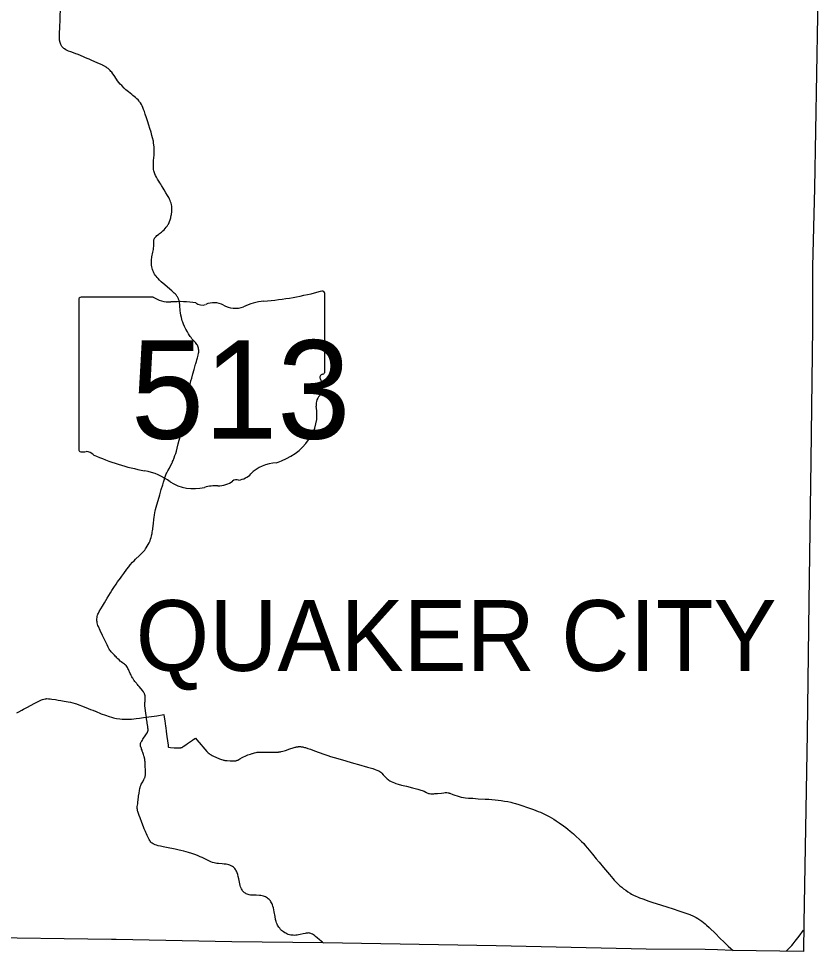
# Model space of a CAD drawing. Extents: x 1761803 to 2441803, y 509895 to 949895.
# Drawn here: x 2301181 to 2323804, y 808156 to 834521 of the extents above; entities that cross this region are included whole.
import ezdxf

# ---------------------------------------------------------------- set-up
doc = ezdxf.new("R2010")
doc.units = 0
for name, color, linetype in [('GM_X_County', 7, 'Continuous'), ('GM_X_County_Road', 7, 'Continuous'), ('GM_X_Minor_Lake', 7, 'Continuous'), ('GM_X_Township_Road', 7, 'Continuous')]:
    doc.layers.add(name, color=color, linetype=linetype)

msp = doc.modelspace()

# ---------------------------------------------------------------- linework, layer by layer
at = {"layer": 'GM_X_County'}
msp.add_lwpolyline([(2323804, 836223), (2323694, 829731), (2323638, 827518), (2323640, 825800), (2323587, 822019), (2323538, 818035), (2323488, 814313), (2323389, 808951), (2323379, 808156), (2321372, 808183), (2320947, 808195), (2320606, 808207), (2318933, 808214), (2314690, 808308), (2309795, 808393), (2307209, 808423), (2303944, 808491), (2303812, 808492), (2299788, 808546)], dxfattribs=at)
at = {"layer": 'GM_X_Minor_Lake'}
for points in [[(2303174, 833376), (2303124, 833396), (2303058, 833425), (2302914, 833485), (2302838, 833514), (2302795, 833530), (2302732, 833552), (2302657, 833579), (2302590, 833605), (2302538, 833630), (2302515, 833642), (2302480, 833665), (2302458, 833682), (2302438, 833700), (2302421, 833718), (2302415, 833726), (2302406, 833738), (2302388, 833768), (2302379, 833786), (2302374, 833795), (2302366, 833816), (2302364, 833819), (2302356, 833843), (2302353, 833853), (2302349, 833870), (2302347, 833883), (2302345, 833892), (2302342, 833908), (2302340, 833935), (2302338, 833982), (2302340, 834041), (2302342, 834110), (2302348, 834272), (2302352, 834497), (2302361, 834861)], [(2303890, 816530), (2303826, 816598), (2303799, 816627), (2303780, 816650), (2303763, 816674), (2303745, 816702), (2303716, 816754), (2303683, 816818), (2303635, 816915), (2303554, 817087), (2303488, 817230), (2303440, 817335), (2303425, 817371), (2303413, 817406), (2303405, 817438), (2303399, 817467), (2303396, 817497), (2303396, 817500), (2303395, 817527), (2303396, 817560), (2303399, 817593), (2303401, 817603), (2303405, 817626), (2303414, 817658), (2303426, 817689), (2303439, 817719), (2303462, 817763), (2303505, 817840), (2303549, 817913), (2303609, 818011), (2303687, 818141), (2303733, 818216), (2303779, 818292), (2303819, 818359), (2303852, 818412), (2303873, 818445), (2303936, 818538), (2303981, 818602), (2304060, 818707), (2304097, 818757), (2304155, 818837), (2304243, 818955), (2304297, 819026), (2304341, 819079), (2304405, 819153), (2304446, 819196), (2304490, 819241), (2304597, 819342), (2304647, 819389), (2304684, 819427), (2304719, 819466), (2304748, 819501), (2304771, 819532), (2304792, 819562), (2304819, 819606), (2304848, 819657), (2304872, 819704), (2304899, 819763), (2304916, 819806), (2304932, 819852), (2304943, 819896), (2304952, 819937), (2304957, 819966), (2304963, 820005), (2304969, 820047), (2304974, 820086), (2304979, 820122), (2304984, 820164), (2304989, 820210), (2304992, 820236), (2304998, 820291), (2305002, 820324), (2305007, 820366), (2305017, 820428), (2305025, 820486), (2305036, 820561), (2305043, 820599), (2305054, 820647), (2305072, 820714), (2305118, 820868), (2305158, 820996), (2305176, 821059), (2305217, 821211), (2305256, 821344), (2305278, 821419), (2305304, 821507), (2305319, 821554), (2305336, 821600), (2305358, 821651), (2305373, 821683), (2305400, 821736), (2305446, 821819), (2305491, 821899), (2305523, 821963), (2305532, 821985), (2305538, 821999), (2305550, 822033), (2305579, 822103), (2305604, 822171), (2305624, 822233), (2305644, 822299), (2305666, 822384), (2305696, 822505), (2305723, 822603), (2305739, 822660), (2305752, 822711), (2305826, 822973), (2305841, 823026), (2305850, 823063), (2305865, 823127), (2305877, 823175), (2305916, 823318), (2305952, 823457), (2305967, 823521), (2305981, 823595), (2305992, 823666), (2306000, 823734), (2306006, 823806), (2306016, 823950), (2306025, 824084), (2306033, 824153), (2306038, 824192), (2306046, 824234), (2306056, 824279), (2306077, 824359), (2306112, 824485), (2306144, 824599), (2306166, 824677), (2306187, 824750), (2306194, 824772), (2306209, 824826), (2306222, 824873), (2306242, 824935), (2306260, 825005), (2306272, 825062), (2306277, 825098), (2306278, 825123), (2306277, 825136), (2306276, 825149), (2306273, 825181), (2306267, 825210), (2306259, 825238), (2306249, 825265), (2306237, 825288), (2306222, 825313), (2306204, 825340), (2306181, 825367), (2306149, 825404), (2306084, 825474), (2306059, 825504), (2306036, 825533), (2306012, 825568), (2305984, 825612), (2305954, 825664), (2305915, 825740), (2305877, 825820), (2305847, 825885), (2305826, 825937), (2305811, 825981), (2305799, 826022), (2305787, 826073), (2305774, 826140), (2305763, 826208), (2305755, 826260), (2305752, 826279), (2305749, 826315), (2305745, 826355), (2305738, 826443), (2305731, 826488), (2305722, 826539), (2305718, 826556), (2305713, 826574), (2305708, 826588), (2305702, 826604), (2305695, 826622), (2305688, 826637), (2305678, 826654), (2305670, 826668), (2305661, 826681), (2305649, 826696), (2305637, 826711), (2305610, 826739), (2305581, 826766), (2305513, 826826), (2305393, 826928), (2305319, 826993), (2305214, 827086), (2305164, 827133), (2305125, 827173), (2305096, 827205), (2305069, 827238), (2305046, 827270), (2305025, 827303), (2305009, 827332), (2304994, 827362), (2304978, 827402), (2304969, 827430), (2304959, 827468), (2304949, 827510), (2304942, 827549), (2304938, 827585), (2304937, 827613), (2304936, 827637), (2304938, 827683), (2304941, 827723), (2304945, 827759), (2304951, 827788), (2304962, 827836), (2304971, 827871), (2304982, 827922), (2304995, 827996), (2305001, 828041), (2305004, 828076), (2305004, 828115), (2305004, 828133), (2305003, 828151), (2305002, 828194), (2305003, 828226), (2305006, 828249), (2305007, 828260), (2305010, 828271), (2305014, 828284), (2305014, 828286), (2305024, 828307), (2305029, 828317), (2305038, 828329), (2305052, 828346), (2305068, 828362), (2305095, 828387), (2305139, 828422), (2305167, 828444), (2305218, 828486), (2305259, 828522), (2305295, 828556), (2305328, 828592), (2305356, 828624), (2305379, 828655), (2305404, 828693), (2305417, 828716), (2305437, 828757), (2305451, 828790), (2305469, 828839), (2305478, 828867), (2305484, 828891), (2305489, 828914), (2305499, 828959), (2305503, 828983), (2305507, 829007), (2305512, 829049), (2305514, 829071), (2305516, 829092), (2305517, 829114), (2305516, 829140), (2305515, 829176), (2305511, 829215), (2305502, 829266), (2305494, 829301), (2305481, 829341), (2305466, 829381), (2305447, 829422), (2305427, 829463), (2305391, 829526), (2305349, 829596), (2305299, 829681), (2305272, 829725), (2305226, 829801), (2305200, 829842), (2305176, 829880), (2305144, 829931), (2305128, 829958), (2305112, 829983), (2305077, 830043), (2305051, 830092), (2305034, 830131), (2305023, 830159), (2305014, 830188), (2305006, 830223), (2304999, 830259), (2304996, 830305), (2304995, 830345), (2304995, 830391), (2304996, 830433), (2304999, 830476), (2305001, 830519), (2305004, 830574), (2305012, 830675), (2305013, 830711), (2305014, 830757), (2305015, 830806), (2305014, 830848), (2305012, 830900), (2305008, 830949), (2305001, 831007), (2304992, 831057), (2304970, 831151), (2304953, 831221), (2304927, 831312), (2304895, 831416), (2304865, 831506), (2304823, 831637), (2304797, 831715), (2304762, 831822), (2304738, 831893), (2304714, 831957), (2304695, 832007), (2304675, 832054), (2304654, 832095), (2304629, 832137), (2304604, 832172), (2304588, 832193), (2304559, 832225), (2304525, 832256), (2304483, 832294), (2304413, 832349), (2304380, 832376), (2304291, 832448), (2304218, 832509), (2304193, 832530), (2304165, 832557), (2304096, 832627), (2304058, 832668), (2304020, 832713), (2303982, 832762), (2303947, 832812), (2303883, 832910), (2303849, 832962), (2303817, 833005), (2303794, 833032), (2303768, 833060), (2303742, 833086), (2303712, 833111), (2303679, 833135), (2303673, 833139), (2303642, 833159), (2303633, 833165), (2303595, 833186), (2303551, 833208), (2303540, 833214), (2303465, 833248), (2303338, 833305), (2303233, 833351), (2303176, 833375), (2303174, 833376)], [(2304753, 815194), (2304756, 815217), (2304758, 815233), (2304759, 815247), (2304760, 815261), (2304762, 815279), (2304762, 815292), (2304763, 815310), (2304763, 815319), (2304763, 815331), (2304762, 815344), (2304762, 815352), (2304761, 815360), (2304761, 815365), (2304760, 815370), (2304759, 815374), (2304758, 815379), (2304757, 815387), (2304756, 815391), (2304755, 815396), (2304753, 815403), (2304753, 815407), (2304751, 815411), (2304750, 815415), (2304749, 815418), (2304748, 815422), (2304746, 815426), (2304738, 815444), (2304734, 815452), (2304725, 815469), (2304712, 815490), (2304682, 815530), (2304644, 815578), (2304591, 815641), (2304565, 815671), (2304542, 815698), (2304524, 815721), (2304511, 815736), (2304497, 815753), (2304487, 815765), (2304471, 815784), (2304451, 815810), (2304444, 815819), (2304428, 815843), (2304408, 815876), (2304400, 815891), (2304384, 815920), (2304369, 815952), (2304356, 815979), (2304339, 816013), (2304320, 816055), (2304310, 816079), (2304292, 816121), (2304274, 816156), (2304258, 816184), (2304239, 816211), (2304221, 816233), (2304203, 816251), (2304194, 816260), (2304180, 816272), (2304152, 816293), (2304120, 816315), (2304085, 816340), (2304057, 816362), (2304022, 816393), (2303989, 816425), (2303961, 816453), (2303936, 816479), (2303914, 816503), (2303890, 816530)], [(2301134, 814903), (2301185, 814931), (2301270, 814974), (2301323, 815001), (2301435, 815062), (2301622, 815158), (2301715, 815207), (2301793, 815247), (2301826, 815263), (2301856, 815274), (2301890, 815285), (2301928, 815294), (2301957, 815298), (2301979, 815299), (2302025, 815298), (2302074, 815293), (2302116, 815288), (2302221, 815271), (2302301, 815257), (2302372, 815245)], [(2302372, 815245), (2302379, 815244), (2302466, 815230), (2302586, 815209), (2302644, 815198), (2302714, 815181), (2302777, 815163), (2302817, 815151), (2302885, 815126), (2302986, 815087), (2303144, 815024), (2303214, 814997), (2303281, 814970), (2303343, 814944), (2303351, 814941)], [(2303351, 814941), (2303518, 814874), (2303638, 814830), (2303738, 814796), (2303807, 814774), (2303864, 814759), (2303906, 814750), (2303954, 814741), (2304042, 814729), (2304114, 814721), (2304177, 814718), (2304243, 814716), (2304266, 814717)], [(2304752, 815088), (2304752, 815091), (2304751, 815100), (2304750, 815112), (2304750, 815124), (2304749, 815135), (2304749, 815146), (2304750, 815156), (2304750, 815162), (2304750, 815168), (2304751, 815179), (2304753, 815194)], [(2304832, 814512), (2304825, 814559), (2304819, 814611), (2304815, 814633), (2304801, 814731), (2304795, 814778), (2304787, 814828), (2304780, 814880), (2304758, 815039), (2304752, 815088)], [(2304266, 814717), (2304308, 814717), (2304377, 814721), (2304440, 814727), (2304508, 814736), (2304605, 814750), (2304771, 814774), (2304795, 814778)], [(2304795, 814778), (2304865, 814785), (2305011, 814807), (2305092, 814818), (2305292, 814853)], [(2305292, 814853), (2305302, 814774), (2305308, 814733), (2305318, 814662), (2305326, 814604), (2305339, 814510)], [(2304684, 814132), (2304699, 814155), (2304717, 814182), (2304736, 814209), (2304746, 814224), (2304760, 814246), (2304778, 814274), (2304795, 814302), (2304822, 814346), (2304829, 814358), (2304834, 814369), (2304837, 814378), (2304840, 814386), (2304842, 814398), (2304843, 814406), (2304843, 814414), (2304843, 814418), (2304843, 814427), (2304842, 814440), (2304839, 814463), (2304836, 814485), (2304832, 814512)], [(2305339, 814510), (2305342, 814489), (2305342, 814487), (2305357, 814373), (2305376, 814230), (2305407, 813989), (2305408, 813982), (2305409, 813976), (2305410, 813968), (2305410, 813967)], [(2306112, 814134), (2306140, 814152), (2306184, 814179), (2306219, 814138), (2306341, 813997), (2306393, 813938), (2306453, 813869), (2306504, 813810), (2306542, 813771), (2306569, 813747), (2306594, 813728), (2306624, 813709), (2306658, 813690), (2306696, 813672), (2306759, 813645), (2306868, 813600), (2306919, 813579), (2306956, 813567), (2306973, 813563), (2306993, 813558), (2307012, 813555), (2307032, 813552), (2307056, 813550), (2307080, 813549), (2307165, 813546), (2307247, 813544), (2307289, 813544), (2307305, 813544), (2307312, 813544)], [(2304726, 813012), (2304742, 813047), (2304748, 813062), (2304752, 813075), (2304756, 813088), (2304760, 813102), (2304764, 813119), (2304767, 813137), (2304768, 813154), (2304769, 813169), (2304770, 813188), (2304770, 813205), (2304768, 813286), (2304764, 813378), (2304762, 813469), (2304759, 813512), (2304755, 813544), (2304751, 813572), (2304748, 813589), (2304743, 813618), (2304740, 813636), (2304737, 813646), (2304735, 813655), (2304734, 813661), (2304732, 813666), (2304727, 813680), (2304714, 813717), (2304693, 813779), (2304680, 813819), (2304672, 813844), (2304661, 813875), (2304654, 813896), (2304649, 813909), (2304633, 813956), (2304631, 813964), (2304629, 813972), (2304627, 813981), (2304626, 813991), (2304625, 813998), (2304625, 814005), (2304625, 814012), (2304625, 814019), (2304627, 814026), (2304630, 814035), (2304632, 814043), (2304637, 814053), (2304642, 814064), (2304647, 814075), (2304654, 814087), (2304662, 814101), (2304681, 814129), (2304684, 814132)], [(2305410, 813967), (2305412, 813958), (2305413, 813952), (2305415, 813942), (2305418, 813931), (2305479, 813921), (2305581, 813913), (2305689, 813906), (2305719, 813905), (2305732, 813906), (2305747, 813908), (2305760, 813910), (2305772, 813912), (2305781, 813915), (2305788, 813917), (2305797, 813920), (2305805, 813923), (2305825, 813934), (2305838, 813943), (2305908, 813992), (2305956, 814027), (2306017, 814071), (2306096, 814124), (2306112, 814134)], [(2307312, 813544), (2307319, 813545), (2307330, 813546), (2307343, 813548), (2307354, 813552), (2307364, 813556), (2307373, 813560), (2307380, 813564), (2307434, 813596), (2307506, 813637), (2307541, 813655), (2307585, 813676), (2307625, 813692), (2307668, 813708), (2307737, 813730), (2307784, 813745), (2307799, 813750), (2307852, 813765), (2307900, 813778), (2307928, 813784), (2307955, 813787), (2307983, 813790), (2308014, 813791), (2308100, 813790), (2308212, 813787), (2308244, 813786), (2308303, 813785), (2308421, 813785), (2308486, 813787), (2308507, 813788), (2308528, 813790), (2308546, 813792), (2308570, 813796), (2308591, 813800), (2308611, 813804), (2308659, 813817), (2308731, 813838), (2308849, 813877), (2308949, 813909), (2309006, 813926), (2309026, 813931), (2309045, 813935), (2309059, 813938), (2309074, 813940), (2309085, 813942), (2309097, 813943), (2309112, 813944), (2309127, 813944), (2309139, 813944), (2309157, 813943), (2309173, 813941), (2309193, 813938), (2309217, 813933), (2309242, 813927), (2309266, 813922), (2309293, 813914), (2309362, 813894), (2309440, 813868), (2309505, 813844), (2309659, 813787), (2309680, 813779), (2309813, 813731), (2309930, 813690), (2310005, 813666), (2310106, 813637), (2310273, 813590), (2310440, 813541), (2310469, 813533), (2310658, 813479), (2310797, 813439), (2311048, 813365), (2311200, 813321), (2311269, 813299), (2311315, 813282), (2311346, 813269), (2311369, 813257), (2311395, 813242), (2311424, 813220), (2311454, 813193), (2311494, 813149), (2311538, 813100), (2311569, 813067), (2311603, 813036), (2311633, 813011), (2311651, 812998), (2311681, 812979), (2311721, 812957), (2311766, 812936), (2311811, 812918), (2311851, 812904), (2311917, 812884), (2312012, 812858), (2312155, 812823), (2312321, 812781), (2312473, 812741), (2312559, 812717), (2312596, 812706), (2312624, 812695), (2312651, 812682), (2312697, 812657), (2312719, 812645), (2312729, 812640), (2312753, 812629), (2312780, 812620), (2312808, 812614), (2312840, 812611), (2312882, 812610), (2312895, 812611), (2312931, 812613), (2312957, 812615), (2313029, 812621), (2313140, 812632), (2313211, 812641), (2313251, 812644), (2313277, 812645), (2313297, 812643), (2313331, 812638), (2313347, 812635), (2313362, 812631), (2313379, 812625), (2313468, 812593), (2313524, 812573), (2313586, 812551), (2313645, 812532), (2313703, 812518), (2313761, 812507), (2313826, 812498), (2313905, 812491), (2313997, 812484), (2314026, 812482), (2314177, 812472), (2314377, 812461), (2314478, 812454), (2314742, 812430), (2314833, 812419), (2314924, 812405), (2315021, 812388), (2315101, 812371), (2315158, 812357), (2315240, 812334), (2315334, 812306), (2315440, 812272), (2315546, 812235), (2315746, 812162), (2315878, 812112), (2315941, 812086), (2316016, 812053), (2316095, 812014), (2316192, 811965), (2316252, 811932), (2316319, 811891), (2316391, 811845), (2316470, 811792), (2316598, 811701), (2316662, 811655), (2316716, 811613), (2316787, 811554), (2316874, 811480), (2316954, 811407), (2317038, 811329), (2317108, 811260), (2317165, 811201), (2317209, 811152), (2317275, 811075), (2317416, 810907), (2317523, 810776)], [(2309807, 808391), (2309777, 808416), (2309751, 808435), (2309743, 808441), (2309690, 808485), (2309628, 808539), (2309581, 808580), (2309550, 808604), (2309521, 808624), (2309493, 808641), (2309467, 808654), (2309443, 808664), (2309419, 808670), (2309396, 808673), (2309377, 808675), (2309351, 808674), (2309319, 808670), (2309284, 808664), (2309227, 808650), (2309144, 808629), (2309099, 808619), (2309057, 808613), (2309020, 808609), (2308987, 808608), (2308948, 808609), (2308912, 808612), (2308879, 808617), (2308840, 808626), (2308806, 808637), (2308772, 808651), (2308739, 808666), (2308708, 808684), (2308674, 808706), (2308645, 808728), (2308620, 808749), (2308592, 808777), (2308566, 808807), (2308540, 808840), (2308521, 808868), (2308505, 808896), (2308490, 808926), (2308476, 808963), (2308464, 809001), (2308452, 809052), (2308434, 809139), (2308409, 809271), (2308387, 809383), (2308375, 809431), (2308363, 809468), (2308350, 809501), (2308336, 809531), (2308320, 809559), (2308306, 809580), (2308289, 809601), (2308267, 809624), (2308243, 809645), (2308217, 809664), (2308189, 809682), (2308161, 809697), (2308134, 809709), (2308104, 809720), (2308072, 809728), (2308037, 809733), (2307992, 809737), (2307903, 809740), (2307808, 809741), (2307775, 809743), (2307739, 809748), (2307706, 809754), (2307678, 809762), (2307650, 809772), (2307620, 809786), (2307597, 809799), (2307575, 809814), (2307554, 809831), (2307535, 809850), (2307518, 809871), (2307501, 809895), (2307486, 809921), (2307474, 809945), (2307460, 809979), (2307449, 810017), (2307438, 810062), (2307410, 810206), (2307394, 810273), (2307380, 810327), (2307367, 810371), (2307355, 810401), (2307342, 810427), (2307328, 810452), (2307313, 810474), (2307297, 810494), (2307276, 810514), (2307255, 810533), (2307228, 810552), (2307195, 810572), (2307173, 810584), (2307152, 810593), (2307125, 810601), (2307090, 810610), (2307049, 810617), (2306997, 810623), (2306942, 810627), (2306838, 810635), (2306789, 810641), (2306750, 810647), (2306708, 810657), (2306667, 810669), (2306621, 810687), (2306576, 810706), (2306508, 810739), (2306370, 810807), (2306317, 810832), (2306260, 810856), (2306193, 810882), (2306140, 810901), (2306078, 810921), (2305984, 810950), (2305858, 810985), (2305773, 811008), (2305719, 811021), (2305606, 811043), (2305364, 811088), (2305268, 811107), (2305191, 811125), (2305131, 811141), (2305080, 811157), (2305046, 811169), (2305003, 811186), (2304983, 811197), (2304957, 811213), (2304941, 811225), (2304922, 811243), (2304899, 811271), (2304890, 811285), (2304872, 811317), (2304851, 811357), (2304817, 811432), (2304797, 811474), (2304780, 811512), (2304767, 811541), (2304736, 811619), (2304714, 811673), (2304695, 811722), (2304683, 811753), (2304666, 811799), (2304616, 811927), (2304590, 811998), (2304571, 812054), (2304553, 812110), (2304548, 812129), (2304545, 812145), (2304542, 812159), (2304540, 812172), (2304539, 812186), (2304538, 812202), (2304538, 812212), (2304538, 812225), (2304539, 812236), (2304539, 812248), (2304549, 812326), (2304552, 812354), (2304555, 812378), (2304557, 812397), (2304560, 812420), (2304576, 812540), (2304590, 812629), (2304602, 812704), (2304611, 812755), (2304619, 812790), (2304623, 812806), (2304629, 812825), (2304635, 812841), (2304641, 812856), (2304652, 812880), (2304672, 812916), (2304691, 812949), (2304726, 813012)], [(2317523, 810776), (2317607, 810673), (2317726, 810529), (2317894, 810327), (2317987, 810217), (2318031, 810169), (2318047, 810151), (2318096, 810099), (2318143, 810053), (2318189, 810011), (2318240, 809968), (2318294, 809926), (2318356, 809882), (2318418, 809839), (2318477, 809803), (2318522, 809776), (2318578, 809747), (2318637, 809718), (2318691, 809694), (2318749, 809670), (2318835, 809638), (2319005, 809579), (2319089, 809551), (2319368, 809463), (2319521, 809414), (2319696, 809358), (2319855, 809305), (2320022, 809249), (2320115, 809216), (2320167, 809195), (2320191, 809186), (2320251, 809160), (2320305, 809135), (2320351, 809111), (2320396, 809084), (2320398, 809083), (2320447, 809050), (2320509, 809006), (2320556, 808971), (2320599, 808936), (2320644, 808898), (2320715, 808831), (2320901, 808650), (2321012, 808539), (2321146, 808408), (2321252, 808305), (2321325, 808239), (2321395, 808179)], [(2322892, 808162), (2322910, 808178), (2322963, 808228), (2323000, 808265), (2323049, 808319), (2323093, 808372), (2323149, 808441), (2323259, 808588), (2323382, 808754)]]:
    msp.add_lwpolyline(points, dxfattribs=at)
at = {"layer": 'GM_X_Township_Road'}
for p, q in [((2302880, 826575), (2302880, 822348)), ((2304987, 826647), (2302949, 826647)), ((2309841, 824541), (2309841, 826752)), ((2309840, 824542), (2309841, 824541))]:
    msp.add_line(p, q, dxfattribs=at)
for centre, major_axis, start_param, end_param in [((2307361, 832410), (7382, 0), 4.814394, 5.042369), ((2309764, 826761), (77.5, 0), 6.141152, 7.989035), ((2302960, 826584), (80.6, 0), 1.712693, 3.28349), ((2305473, 827138), (782, 0), 4.042523, 4.731795), ((2305732, 824275), (2808, 0), 1.404758, 1.657858), ((2306369, 826606), (226, 0), 3.836095, 5.185415), ((2306701, 826117), (469, 0), 0.950623, 2.079405), ((2307306, 826787), (564, 0), 4.081561, 5.145723), ((2308303, 825357), (1485, 0), 1.699011, 2.107814), ((2309823, 824379), (120, 0), 1.883978, 3.671073), ((2309758, 824533), (82.9, 0), 5.05454, 6.418171), ((2309060, 824099), (720, 0), 5.934695, 6.695948), ((2310119, 823616), (524, 0), 2.387724, 3.262537), ((2307775, 823335), (1846, 0), 5.101752, 6.440018), ((2302961, 822339), (81.4, 0), 3.00124, 4.508301), ((2302973, 822771), (621, 0), 4.665946, 4.897461), ((2303100, 822104), (224, 0), 0.519207, 1.627899), ((2305926, 825902), (5331, 0), 4.195997, 4.488961), ((2308553, 821162), (1011, 0), 1.647645, 2.488434), ((2304337, 820449), (1668, 0), 0.823519, 1.323587), ((2307272, 821939), (597, 0), 4.937069, 5.64225), ((2306141, 822083), (1058, 0), 4.026481, 4.996735), ((2306753, 820622), (870, 0), 1.495662, 1.94098), ((2306830, 821767), (564, 0), 4.691044, 5.507374), ((2307340, 821358), (159, 0), 1.147584, 2.315152)]:
    msp.add_ellipse(centre, major_axis=major_axis, ratio=0.8, start_param=start_param, end_param=end_param, dxfattribs=at)

# ---------------------------------------------------------------- texts
at = {"layer": 'GM_X_County_Road'}
msp.add_text('QUAKER CITY', height=2000, rotation=0, dxfattribs=at).set_placement((2304492, 816084))
at = {"layer": 'GM_X_Township_Road'}
msp.add_text('513', height=2784.4, dxfattribs=at).set_placement((2304356, 822646))

doc.saveas('drawing.dxf')
